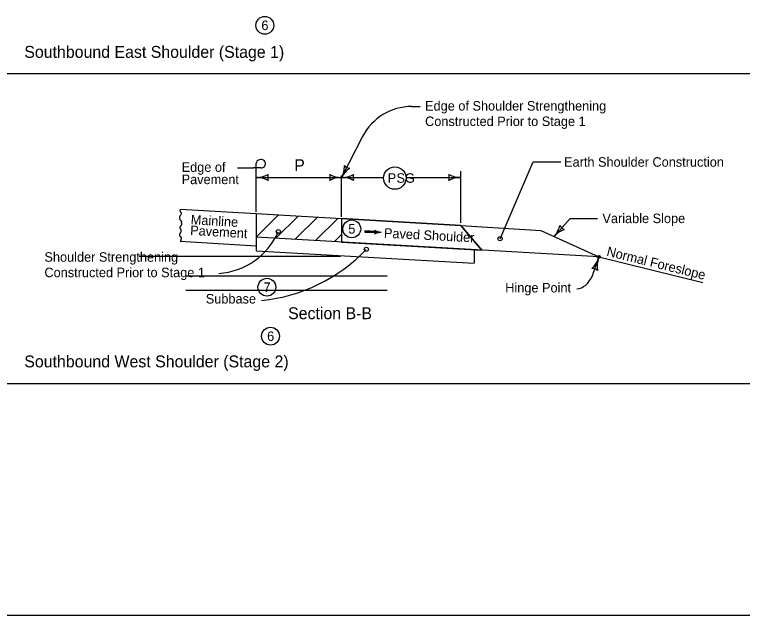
# Model space of a CAD drawing. Extents: x 8045 to 81668, y 6217 to 16762.
# Drawn here: x 11002 to 12226, y 7924 to 8935 of the extents above; entities that cross this region are included whole.
import ezdxf

# ---------------------------------------------------------------- set-up
doc = ezdxf.new("R2010")
doc.units = 0
for name, color, linetype in [('dsnStdDetailExtension', 7, 'Continuous'), ('dsnStdDimension', 7, 'Continuous'), ('dsnStdLabel', 7, 'Continuous'), ('dsnStdLineWork', 7, 'Continuous'), ('dsnStdPattern', 7, 'Continuous'), ('dsnStdSection', 7, 'Continuous'), ('Level 4', 7, 'Continuous'), ('Level 8', 7, 'Continuous')]:
    doc.layers.add(name, color=color, linetype=linetype)

msp = doc.modelspace()

# ---------------------------------------------------------------- linework, layer by layer
at = {"layer": 'dsnStdDetailExtension'}
for centre in [(11446, 8570), (11446, 8570), (11818.9, 8558.2), (11818.9, 8558.2), (11593.9, 8540.2), (11593.9, 8540.2)]:
    msp.add_circle(centre, 3.54, dxfattribs=at)
at = {"layer": 'dsnStdDimension'}
msp.add_line((10152.2, 8314.4), (13247.9, 8314.4), dxfattribs=at)
at = {"layer": 'dsnStdLabel'}
for p, q in [((11281.2, 8607.8), (11408.7, 8600.4)), ((11408.7, 8600.4), (11408.7, 8546.4)), ((11408.7, 8600.4), (11753, 8580.4)), ((11552.4, 8592.1), (11552.4, 8552.2)), ((11752.5, 8580.6), (11752.5, 8580.6)), ((11753, 8580.5), (11887.7, 8572.1)), ((11753, 8580.4), (11788, 8539)), ((11887.7, 8572.1), (11984.8, 8527.6)), ((11984.8, 8527.6), (11408.7, 8560.8)), ((11281.2, 8553.8), (11408.7, 8546.4)), ((11408.7, 8546.4), (11408.7, 8538)), ((11775.2, 8554.1), (11775.2, 8554.1)), ((11408.7, 8538), (11775.2, 8516.9)), ((11775.2, 8539.7), (11775.2, 8516.9)), ((11212, 8528.5), (11550.5, 8528.5)), ((11984.8, 8527.6), (12159.8, 8484.3)), ((11290.6, 8495.5), (11629.1, 8495.5)), ((11290.6, 8471.8), (11629.1, 8471.8))]:
    msp.add_line(p, q, dxfattribs=at)
msp.add_ellipse((11984.8, 8527.6), major_axis=(2.58, 0), ratio=0.913811, dxfattribs=at)
for points in [[(11281.2, 8607.8), (11280.7, 8604.2), (11281.8, 8602.7), (11282.6, 8600.4), (11282, 8598.4), (11280.1, 8596), (11279.6, 8594.1), (11280.1, 8591.8), (11281, 8589.4), (11282, 8588.7), (11283.4, 8586.2), (11283.4, 8585.3)], [(11281.4, 8568.2), (11281.6, 8568.5), (11281.8, 8568.7), (11282.2, 8569.3), (11282.5, 8569.9), (11282.6, 8570.2), (11282.7, 8570.5), (11282.8, 8571.1), (11282.9, 8571.7), (11282.8, 8572.3), (11282.8, 8572.6), (11282.7, 8572.7), (11282.7, 8572.9), (11282.5, 8573.2), (11282.2, 8573.6), (11281.9, 8574), (11281.6, 8574.4), (11281.5, 8574.7), (11281.4, 8574.9), (11281.1, 8575.5), (11280.9, 8576.1), (11280.8, 8576.4), (11280.8, 8576.7), (11280.8, 8576.8), (11280.8, 8576.9), (11280.9, 8577.7), (11281.1, 8578.2), (11281.4, 8578.7), (11281.8, 8579.4), (11282.3, 8579.9), (11282.9, 8580.5), (11283.1, 8580.8), (11283.3, 8581.1), (11283.5, 8581.6), (11283.6, 8582.1), (11283.8, 8582.5), (11283.8, 8582.8), (11283.8, 8582.9), (11283.8, 8583), (11283.8, 8583.5), (11283.6, 8584), (11283.6, 8584.2), (11283.5, 8584.3), (11283.5, 8584.4), (11283.4, 8584.5), (11283.4, 8585.3)], [(11281.4, 8568.2), (11281.2, 8568), (11281, 8567.8), (11280.7, 8567.5), (11280.5, 8567.2), (11280.4, 8567), (11280.3, 8566.7), (11280, 8566.1), (11279.9, 8565.8), (11279.8, 8565.5), (11279.7, 8565.2), (11279.7, 8565.1), (11279.7, 8564.9), (11279.7, 8564.4), (11279.8, 8563.9), (11280, 8563.4), (11280.3, 8562.9), (11280.7, 8562.2), (11281.3, 8561.7), (11281.8, 8561.2), (11282, 8560.8), (11282.2, 8560.5), (11282.6, 8559.6), (11282.7, 8559.1), (11282.7, 8558.6), (11282.7, 8558.3), (11282.6, 8558), (11282.6, 8557.7), (11282.5, 8557.5), (11282.2, 8556.3), (11282, 8555.7), (11281.8, 8555.1), (11281.6, 8554.5), (11281.5, 8554.2), (11281.3, 8553.9), (11281.2, 8553.8)]]:
    msp.add_spline(points, degree=3, dxfattribs=at)
at = {"layer": 'dsnStdLineWork'}
for p, q in [((11670.1, 8780.7), (11684.4, 8780.7)), ((11587.8, 8730.3), (11552.4, 8661.2)), ((11408.7, 8664.5), (11408.7, 8685.3)), ((11818.9, 8558.2), (11874.6, 8687.3)), ((11874.6, 8687.3), (11921, 8687.3)), ((11377.3, 8677.3), (11404, 8677.3)), ((11416.5, 8677.3), (11404, 8677.3)), ((11753, 8585), (11753, 8671.7)), ((11408.7, 8603.6), (11408.7, 8664.5)), ((11408.7, 8661.2), (11623, 8661.2)), ((11552.4, 8594.9), (11552.4, 8664.5)), ((11660.8, 8661.3), (11753, 8661.3)), ((11408.7, 8560.8), (11446.5, 8598.2)), ((11441.7, 8558.9), (11479.5, 8596.3)), ((11474, 8557.1), (11511.8, 8594.5)), ((11508.6, 8555.1), (11546.4, 8592.5)), ((11909.9, 8561.9), (11936.5, 8592.4)), ((11936.5, 8592.4), (11982.9, 8592.4)), ((11609.7, 8569.3), (11591.5, 8570.4)), ((11609.6, 8568.4), (11609.6, 8568.4)), ((11609.7, 8570.3), (11609.7, 8570.3)), ((11540.2, 8553.2), (11552.4, 8565.4)), ((11975, 8497.7), (11984.5, 8525.3))]:
    msp.add_line(p, q, dxfattribs=at)
for points in [[(11609.7, 8570.3), (11591.6, 8571.3), (11591.4, 8569.4), (11609.6, 8568.4), (11609.7, 8570), (11591.8, 8571.1), (11591.7, 8569.6), (11609.2, 8568.6), (11609.3, 8569.8), (11592, 8570.8), (11592, 8569.8), (11609, 8568.8), (11609.1, 8569.5), (11592.2, 8570.6), (11592.2, 8570), (11608.8, 8569.1)], [(11609.3, 8571.5), (11610, 8570.3), (11610, 8568.7), (11609.2, 8567.3), (11612, 8568.2), (11615.2, 8568.8), (11616.1, 8568.9), (11613.8, 8569.5), (11610.6, 8570.7), (11609.7, 8571.3), (11609.8, 8567.7), (11614.7, 8569), (11610.1, 8570.5), (11610.1, 8568.1), (11613.5, 8569.1), (11610.5, 8569.9), (11610.3, 8568.5), (11612.4, 8569), (11610.9, 8569.5), (11610.7, 8568.9), (11611.5, 8569)]]:
    msp.add_lwpolyline(points, dxfattribs=at)
msp.add_circle((11641.9, 8660.3), 18.9, dxfattribs=at)
for centre, radius, start, end in [((11670.1, 8688.3), 92.4, 90, 152.9341), ((11514.6, 8680.5), 42.5, 332.9341, 1.0066), ((11568.7, 8692.9), 16.4, 225.2008, 260.6675), ((11408.7, 8703.7), 42.5, 270, 298.0725), ((11444.3, 8661.2), 16.4, 162.2666, 197.7334), ((11516.8, 8661.2), 16.4, 342.2666, 17.7334), ((11552.4, 8703.7), 42.5, 241.9275, 270), ((11590.3, 8641.8), 42.5, 124.8616, 152.9341), ((11552.4, 8703.7), 42.5, 270, 298.0725), ((11588.1, 8661.2), 16.4, 162.2666, 197.7334), ((11717.3, 8661.3), 16.4, 342.2666, 17.7333), ((11753, 8703.8), 42.5, 241.9275, 270), ((11408.7, 8618.7), 42.5, 61.9275, 90), ((11552.4, 8618.7), 42.5, 90, 118.0725), ((11552.4, 8618.7), 42.5, 61.9275, 90), ((11753, 8618.8), 42.5, 90, 118.0725), ((11877.9, 8589.9), 42.5, 318.8454, 346.9178), ((11933.4, 8588.8), 16.4, 211.112, 246.5787), ((11337.4, 8618.2), 118.9, 274.0851, 336.0699), ((11941.9, 8534), 42.5, 110.7729, 138.8454), ((11390, 8734.9), 282, 275.6784, 316.2844), ((11944.3, 8539.1), 42.5, 312.9788, 341.0513), ((12024.7, 8511.5), 42.5, 161.0513, 189.1238), ((11972.9, 8491.6), 16.4, 53.3179, 88.7846)]:
    msp.add_arc(centre, radius, start, end, dxfattribs=at)
for centre, major_axis, ratio, start_param, end_param in [((11416.5, 8684.5), (-7.81, 0), 0.913811, 1.570796, 6.283185), ((11605.9, 8569.5), (3.88, 0), 0.913811, 5.202895, 7.237436), ((11618.2, 8548.5), (22.2, 0), 0.913811, 1.537172, 2.061295), ((11621, 8588.9), (-22.2, 0), 0.913811, 0.954258, 1.478381), ((11947.9, 8535.5), (0, 61.5), 0.559383, 3.141593, 4.048985)]:
    msp.add_ellipse(centre, major_axis=major_axis, ratio=ratio, start_param=start_param, end_param=end_param, dxfattribs=at)
at = {"layer": 'dsnStdPattern'}
for p, q in [((11552.5, 8592.1), (11552.4, 8552.2)), ((11753, 8580.5), (11552.5, 8592.1)), ((11788, 8539), (11753, 8580.5)), ((11552.4, 8552.2), (11788, 8539))]:
    msp.add_line(p, q, dxfattribs=at)
at = {"layer": 'dsnStdSection'}
msp.add_lwpolyline([(10132.5, 9944), (13267.5, 9944), (13267.5, 7924), (10132.5, 7924)], close=True, dxfattribs=at)
at = {"layer": 'Level 4'}
msp.add_line((12307.8, 8835.4), (10152.2, 8835.4), dxfattribs=at)
at = {"layer": 'Level 8'}
for centre in [(11423.3, 8917.3), (11569.5, 8574.7), (11426.8, 8476.5), (11432.9, 8394.1)]:
    msp.add_circle(centre, 15, dxfattribs=at)

# ---------------------------------------------------------------- texts
at = {"layer": 'dsnStdLineWork'}
for s, height, p in [('Southbound East Shoulder (Stage 1)', 20, (11018.8, 8862.6)), ('Edge of Shoulder Strengthening', 16, (11692.8, 8773.8)), ('Constructed Prior to Stage 1', 16, (11692.8, 8747.8)), ('P', 20, (11472.8, 8671.9)), ('Earth Shoulder Construction', 16, (11926.5, 8679.3)), ('Edge of ', 16, (11283.4, 8670.7)), ('Pavement', 16, (11283.4, 8650)), ('P', 16, (11629.8, 8652.3)), ('SG', 16, (11644.7, 8652.3)), ('Variable Slope', 16, (11991, 8584.4)), ('Shoulder Strengthening', 16, (11052.7, 8519.4)), ('Constructed Prior to Stage 1', 16, (11052.7, 8493.4)), ('Hinge Point', 16, (11827.6, 8467.7)), ('Subbase', 16, (11324, 8449.1)), ('Section B-B', 20, (11462.4, 8422.7)), ('Southbound West Shoulder (Stage 2)', 20, (11018.8, 8341.6))]:
    msp.add_text(s, height=height, dxfattribs=at).set_placement(p)
for s, rotation, p in [('Mainline', 356.7346, (11298.4, 8582.5)), ('Pavement', 356.7346, (11297.4, 8564.5)), ('Paved Shoulder ', 356.983, (11623.3, 8560)), ('Normal Foreslope', 346.0988, (11997, 8529.7))]:
    msp.add_text(s, height=16, rotation=rotation, dxfattribs=at).set_placement(p)
at = {"layer": 'Level 8'}
for s, p in [('6', (11417.5, 8909.3)), ('5', (11563.7, 8566.7)), ('7', (11421.1, 8468.5)), ('6', (11427.2, 8386.1))]:
    msp.add_text(s, height=16, dxfattribs=at).set_placement(p)

doc.saveas('drawing.dxf')
